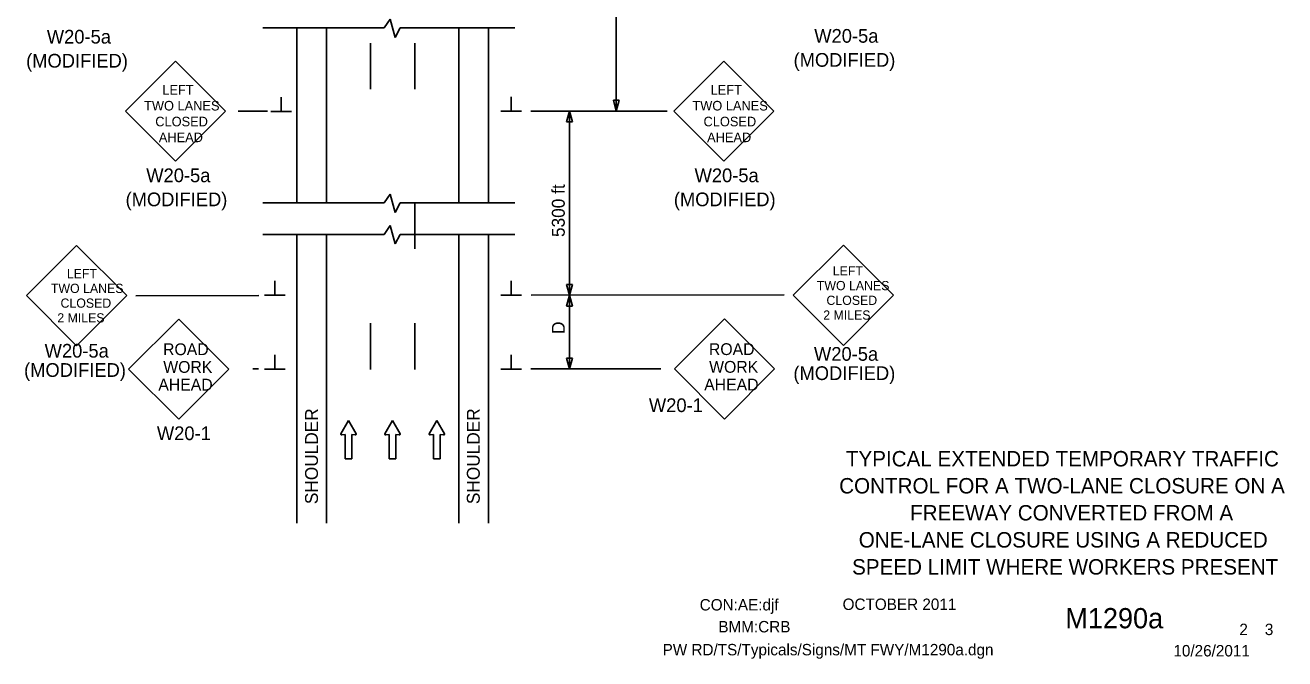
# Model space of a CAD drawing. Extents: x 16590 to 19504, y 5703 to 6974.
# Drawn here: x 17753 to 18437, y 5932 to 6276 of the extents above; entities that cross this region are included whole.
import ezdxf

# ---------------------------------------------------------------- set-up
doc = ezdxf.new("R2010")
doc.units = 0
for name, color, linetype in [('ALI_LEGAL_EX', 7, 'Continuous'), ('BORDER', 7, 'Continuous'), ('BORDER_SIGNAL_WO', 7, 'Continuous'), ('MT_SCRATCH_LEVEL_E', 7, 'Continuous'), ('PAVT_EDGE_EX', 7, 'Continuous'), ('TRAFFIC_SIGNS_PR', 7, 'Continuous'), ('TYPICAL_TEXT_DIMEN_PR', 7, 'Continuous')]:
    doc.layers.add(name, color=color, linetype=linetype)

msp = doc.modelspace()

# ---------------------------------------------------------------- linework, layer by layer
at = {"layer": 'ALI_LEGAL_EX'}
for points in [[(17940.96, 6266), (17940.96, 6241)], [(17964.96, 6266), (17964.96, 6241)], [(17964.96, 6154.34), (17964.96, 6179.34)], [(17940.96, 6113.94), (17940.96, 6088.94)], [(17964.96, 6113.94), (17964.96, 6088.94)]]:
    msp.add_lwpolyline(points, dxfattribs=at)
at = {"layer": 'MT_SCRATCH_LEVEL_E'}
for p, q in [((17928.96, 6061.24), (17924.85, 6054)), ((17933.1, 6054), (17928.96, 6061.24)), ((17952.86, 6061.24), (17948.75, 6054)), ((17957.01, 6054), (17952.86, 6061.24)), ((17976.91, 6061.24), (17972.8, 6054)), ((17981.06, 6054), (17976.91, 6061.24)), ((17925.33, 6053.32), (17927.1, 6053.63)), ((17927.1, 6053.63), (17927.1, 6040.38)), ((17930.85, 6040.38), (17930.85, 6053.63)), ((17930.85, 6053.63), (17932.62, 6053.32)), ((17949.23, 6053.32), (17951.01, 6053.63)), ((17951.01, 6053.63), (17951.01, 6040.38)), ((17954.75, 6040.38), (17954.75, 6053.63)), ((17954.75, 6053.63), (17956.53, 6053.32)), ((17973.28, 6053.32), (17975.06, 6053.63)), ((17975.06, 6053.63), (17975.06, 6040.38)), ((17978.8, 6040.38), (17978.8, 6053.63)), ((17978.8, 6053.63), (17980.58, 6053.32)), ((17927.1, 6040.38), (17930.85, 6040.38)), ((17951.01, 6040.38), (17954.75, 6040.38)), ((17975.06, 6040.38), (17978.8, 6040.38))]:
    msp.add_line(p, q, dxfattribs=at)
for centre, start, end in [((17925.25, 6053.78), 150.42484, 279.96381), ((17932.69, 6053.78), 260.03619, 29.77312), ((17949.16, 6053.78), 150.42484, 279.96381), ((17956.6, 6053.78), 260.03619, 29.77312), ((17973.21, 6053.78), 150.42484, 279.96381), ((17980.65, 6053.78), 260.03619, 29.77312)]:
    msp.add_arc(centre, 0.463, start, end, dxfattribs=at)
at = {"layer": 'PAVT_EDGE_EX'}
for p, q in [((17900.96, 6274.27), (17900.96, 6179.3)), ((17916.96, 6274.27), (17916.96, 6179.3)), ((17988.96, 6274.27), (17988.96, 6179.3)), ((18004.96, 6274.27), (18004.96, 6179.3)), ((17900.96, 6162.17), (17900.96, 6005.43)), ((17916.96, 6162.17), (17916.96, 6005.43)), ((17988.96, 6162.17), (17988.96, 6005.43)), ((18004.96, 6162.17), (18004.96, 6005.43))]:
    msp.add_line(p, q, dxfattribs=at)
at = {"layer": 'TRAFFIC_SIGNS_PR'}
for p, q in [((17835.07, 6256.28), (17807.92, 6229.13)), ((17862.22, 6229.13), (17835.07, 6256.28)), ((18132.81, 6256.28), (18105.66, 6229.13)), ((18159.97, 6229.13), (18132.81, 6256.28)), ((17807.92, 6229.13), (17835.07, 6201.98)), ((17835.07, 6201.98), (17862.22, 6229.13)), ((18105.66, 6229.13), (18132.81, 6201.98)), ((18132.81, 6201.98), (18159.97, 6229.13)), ((18197.7, 6156.32), (18170.51, 6129.14)), ((18224.88, 6129.14), (18197.7, 6156.32)), ((17781.32, 6156.15), (17754.14, 6128.96)), ((17808.51, 6128.96), (17781.32, 6156.15)), ((17754.14, 6128.96), (17781.32, 6101.77)), ((17781.32, 6101.77), (17808.51, 6128.96)), ((18170.51, 6129.14), (18197.7, 6101.95)), ((18197.7, 6101.95), (18224.88, 6129.14)), ((17836.75, 6116.28), (17809.59, 6089.13)), ((17863.9, 6089.13), (17836.75, 6116.28)), ((18133.17, 6116.35), (18105.99, 6089.16)), ((18160.36, 6089.16), (18133.17, 6116.35)), ((17809.59, 6089.13), (17836.75, 6061.97)), ((17836.75, 6061.97), (17863.9, 6089.13)), ((18105.99, 6089.16), (18133.17, 6061.97)), ((18133.17, 6061.97), (18160.36, 6089.16))]:
    msp.add_line(p, q, dxfattribs=at)
at = {"layer": 'TYPICAL_TEXT_DIMEN_PR'}
for p, q in [((18074.39, 6504.84), (18074.39, 6229.16)), ((17948.31, 6274.27), (17882.36, 6274.27)), ((17951.56, 6279.07), (17948.31, 6274.27)), ((17954.3, 6269.13), (17951.56, 6279.07)), ((17957.05, 6274.27), (17954.3, 6269.13)), ((18019.38, 6274.27), (17957.05, 6274.27)), ((17892.33, 6228.9), (17892.33, 6236.69)), ((18017.33, 6229.16), (18017.33, 6236.95)), ((18074.39, 6229.16), (18072.82, 6235.02)), ((18072.82, 6235.02), (18074.39, 6235.02)), ((18074.39, 6235.02), (18075.97, 6235.02)), ((18075.97, 6235.02), (18074.39, 6229.16)), ((17884.97, 6229.16), (17869.02, 6229.16)), ((17897.96, 6228.9), (17886.71, 6228.9)), ((18022.96, 6229.16), (18011.71, 6229.16)), ((18102.08, 6229.16), (18027.96, 6229.16)), ((18047.39, 6223.3), (18048.96, 6229.16)), ((18048.96, 6229.16), (18048.96, 6129.16)), ((18048.96, 6229.16), (18050.53, 6223.3)), ((18048.96, 6223.3), (18047.39, 6223.3)), ((18050.53, 6223.3), (18048.96, 6223.3)), ((17951.56, 6184.1), (17948.31, 6179.3)), ((17954.3, 6174.16), (17951.56, 6184.1)), ((17948.31, 6179.3), (17882.36, 6179.3)), ((17957.05, 6179.3), (17954.3, 6174.16)), ((18019.38, 6179.3), (17957.05, 6179.3)), ((17951.56, 6166.97), (17948.31, 6162.17)), ((17954.3, 6157.03), (17951.56, 6166.97)), ((17948.31, 6162.17), (17882.36, 6162.17)), ((17957.05, 6162.17), (17954.3, 6157.03)), ((18019.38, 6162.17), (17957.05, 6162.17)), ((17889, 6129.16), (17889, 6136.95)), ((18017.33, 6129.16), (18017.33, 6136.95)), ((17880.29, 6128.96), (17813.55, 6128.87)), ((17894.63, 6129.16), (17883.38, 6129.16)), ((18022.96, 6129.16), (18011.71, 6129.16)), ((18165.52, 6129.35), (18028.1, 6129.16)), ((18048.96, 6129.16), (18047.39, 6135.02)), ((18047.39, 6135.02), (18048.96, 6135.02)), ((18047.39, 6123.3), (18048.96, 6129.16)), ((18048.96, 6135.02), (18050.53, 6135.02)), ((18050.53, 6135.02), (18048.96, 6129.16)), ((18048.96, 6129.16), (18048.96, 6089.16)), ((18048.96, 6129.16), (18050.53, 6123.3)), ((18048.96, 6123.3), (18047.39, 6123.3)), ((18050.53, 6123.3), (18048.96, 6123.3)), ((17889, 6089.11), (17889, 6096.9)), ((18017.33, 6089.11), (18017.33, 6096.9)), ((18048.96, 6089.16), (18047.39, 6095.02)), ((18047.39, 6095.02), (18048.96, 6095.02)), ((18048.96, 6095.02), (18050.53, 6095.02)), ((18050.53, 6095.02), (18048.96, 6089.16)), ((17880.16, 6089.16), (17877, 6089.16)), ((17894.63, 6089.11), (17883.38, 6089.11)), ((18022.96, 6089.11), (18011.71, 6089.11)), ((18098.6, 6089.16), (18027.96, 6089.16))]:
    msp.add_line(p, q, dxfattribs=at)

# ---------------------------------------------------------------- texts
at = {"layer": 'BORDER'}
for s, p in [('TYPICAL EXTENDED TEMPORARY TRAFFIC', (18199.06, 6036.26)), ('CONTROL FOR A TWO-LANE CLOSURE ON A', (18195.43, 6021.58)), ('FREEWAY CONVERTED FROM A', (18233.93, 6006.91)), ('ONE-LANE CLOSURE USING A REDUCED', (18206.04, 5992.23)), ('SPEED LIMIT WHERE WORKERS PRESENT', (18202.43, 5977.56))]:
    msp.add_text(s, height=8.3734, dxfattribs=at).set_placement(p)
at = {"layer": 'BORDER_SIGNAL_WO'}
for s, height, p in [('    OCTOBER 2011    ', 6.2, (18188.08, 5958.34)), ('CON:AE:djf  ', 6.2, (18119.69, 5958.06)), ('    M1290a   ', 11, (18301.86, 5948.38)), ('BMM:CRB   ', 6.2, (18129.81, 5946.17)), (' 2    3 ', 6.2, (18410.45, 5944.7)), ('PW RD/TS/Typicals/Signs/MT FWY/M1290a.dgn      ', 6.2, (18099.55, 5933.71)), ('10/26/2011    ', 6.2, (18376.93, 5933.13))]:
    msp.add_text(s, height=height, dxfattribs=at).set_placement(p)
at = {"layer": 'TRAFFIC_SIGNS_PR'}
for s, height, p in [('W20-5a', 7.44, (17765.15, 6265.79)), ('W20-5a', 7.44, (18181.9, 6266.24)), ('(MODIFIED)', 7.44, (17753.91, 6252.75)), ('(MODIFIED)', 7.44, (18170.66, 6253.2)), ('LEFT', 5.2, (17827.88, 6238.06)), ('LEFT', 5.2, (18125.62, 6238.06)), ('TWO LANES', 5.2, (17817.98, 6229.46)), ('TWO LANES', 5.2, (18115.72, 6229.46)), ('CLOSED', 5.2, (17824.03, 6220.86)), ('CLOSED', 5.2, (18121.77, 6220.86)), ('AHEAD', 5.2, (17825.96, 6212.26)), ('AHEAD', 5.2, (18123.7, 6212.26)), ('W20-5a', 7.44, (17819.15, 6190.54)), ('W20-5a', 7.44, (18116.9, 6190.54)), ('(MODIFIED)', 7.44, (17807.91, 6177.5)), ('(MODIFIED)', 7.44, (18105.65, 6177.5)), ('LEFT', 5.006, (17776.01, 6138.42)), ('LEFT', 5.006, (18191.94, 6139.93)), ('TWO LANES', 5.006, (18183.29, 6131.92)), ('TWO LANES', 5.006, (17767.36, 6130.41)), ('CLOSED', 5.006, (18188.52, 6123.92)), ('CLOSED', 5.006, (17772.59, 6122.4)), ('2 MILES', 5.006, (17770.84, 6114.39)), ('2 MILES', 5.006, (18186.77, 6115.91)), ('W20-5a', 7.449, (17763.94, 6095.32)), ('ROAD', 6.4, (17828.29, 6096.66)), ('ROAD', 6.408, (18124.7, 6096.71)), ('W20-5a', 7.449, (18181.72, 6093.61)), ('(MODIFIED)', 7.449, (17752.78, 6084.87)), ('WORK', 6.4, (17828.4, 6087.06)), ('WORK', 6.408, (18124.81, 6087.1)), ('(MODIFIED)', 7.449, (18170.56, 6083.16)), ('AHEAD', 6.4, (17825.71, 6077.46)), ('AHEAD', 6.408, (18122.12, 6077.48)), ('W20-1', 7.449, (18092.09, 6065.76)), ('W20-1', 7.44, (17824.92, 6050.54))]:
    msp.add_text(s, height=height, dxfattribs=at).set_placement(p)
at = {"layer": 'TYPICAL_TEXT_DIMEN_PR'}
for s, p in [('5300 ft', (18046.4, 6160.77)), ('D', (18046.4, 6108.17)), ('SHOULDER', (17912.38, 6015.79)), ('SHOULDER', (18000.24, 6015.79))]:
    msp.add_text(s, height=7, rotation=90, dxfattribs=at).set_placement(p)

doc.saveas('drawing.dxf')
